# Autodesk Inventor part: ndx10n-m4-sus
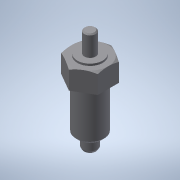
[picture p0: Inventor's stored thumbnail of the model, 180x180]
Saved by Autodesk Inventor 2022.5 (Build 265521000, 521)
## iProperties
Created: 2016-12
Part Number: ndx10n-m4-sus
Material: 一般
Document SubType Name: Modeling
Designer: imaocorp
Density: 1 g/cm^3
Appearance: 既定
Author: imaocorp
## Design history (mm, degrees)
node "ndx10n-m4-sus.x_t1"
node "ndx10n-m4-sus"
node "Base1"
